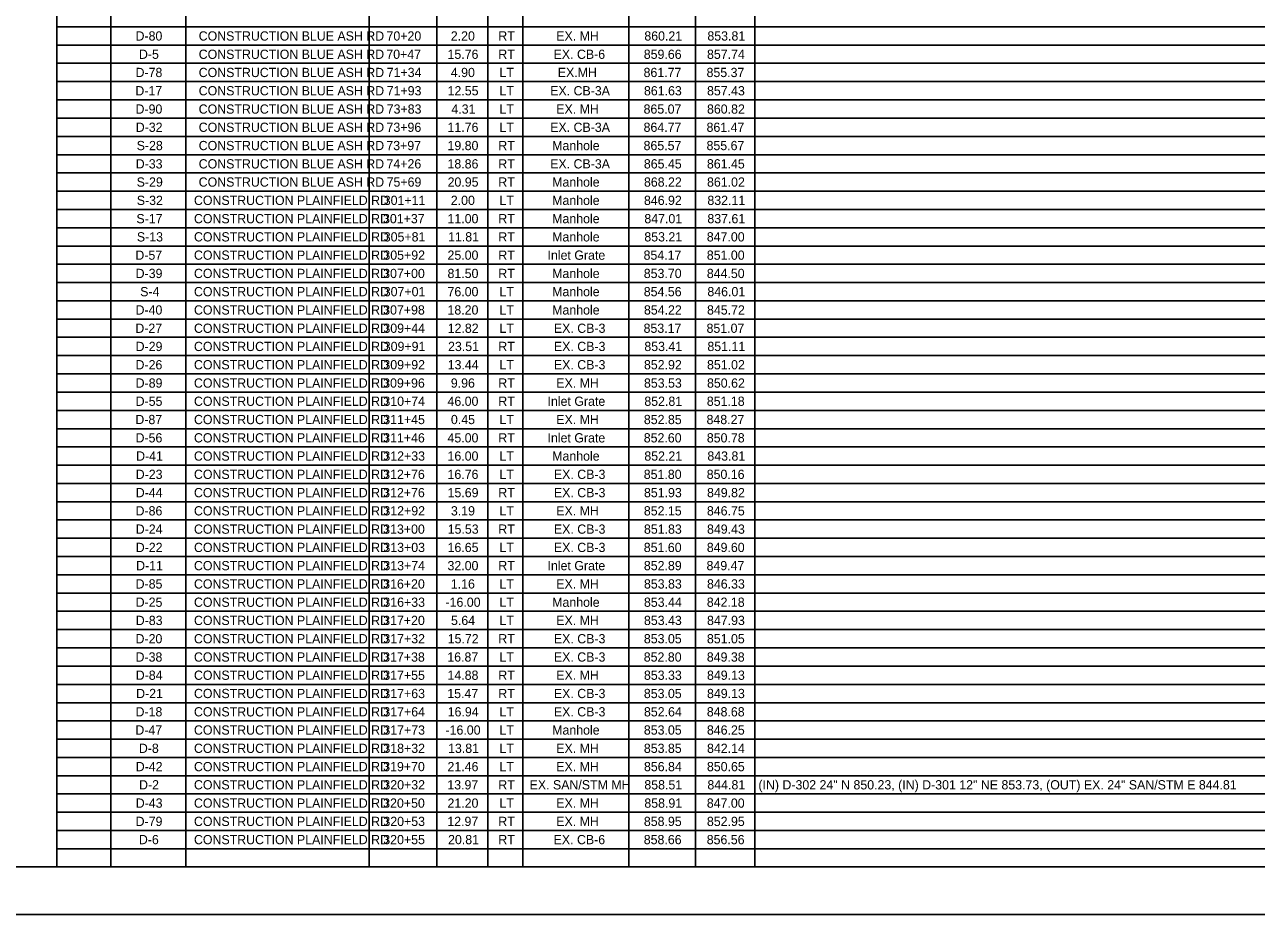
# Model space of a CAD drawing. Extents: x 0 to 34, y 0 to 22.
# Drawn here: x 12.56 to 25.55, y 0 to 9.39 of the extents above; entities that cross this region are included whole.
import ezdxf

# ---------------------------------------------------------------- set-up
doc = ezdxf.new("R2010")
doc.units = 0
for name, color, linetype in [('SH_Border', 7, 'Continuous'), ('SH_Cut_Line', 7, 'Continuous'), ('SH_Text', 7, 'Continuous')]:
    doc.layers.add(name, color=color, linetype=linetype)

msp = doc.modelspace()

# ---------------------------------------------------------------- linework, layer by layer
at = {"layer": 'SH_Border'}
msp.add_lwpolyline([(1.5, 21.5), (33.5, 21.5), (33.5, 0.5), (1.5, 0.5)], close=True, dxfattribs=at)
at = {"layer": 'SH_Cut_Line'}
msp.add_lwpolyline([(0, 0), (34, 0), (34, 22), (0, 22)], close=True, dxfattribs=at)
at = {"layer": 'SH_Text'}
for p, q in [((12.897, 21.5), (12.897, 0.5)), ((13.466, 21.307), (13.466, 0.5)), ((14.256, 21.307), (14.256, 0.5)), ((16.192, 21.307), (16.192, 0.5)), ((16.905, 21.307), (16.905, 0.5)), ((17.444, 21.307), (17.444, 0.5)), ((17.81, 21.307), (17.81, 0.5)), ((18.928, 21.307), (18.928, 0.5)), ((19.631, 21.307), (19.631, 0.5)), ((20.257, 21.307), (20.257, 0.5)), ((12.897, 9.362), (29.601, 9.362)), ((12.897, 9.169), (29.601, 9.169)), ((12.897, 8.977), (29.601, 8.977)), ((12.897, 8.784), (29.601, 8.784)), ((12.897, 8.591), (29.601, 8.591)), ((12.897, 8.399), (29.601, 8.399)), ((12.897, 8.206), (29.601, 8.206)), ((12.897, 8.013), (29.601, 8.013)), ((12.897, 7.821), (29.601, 7.821)), ((12.897, 7.628), (29.601, 7.628)), ((12.897, 7.435), (29.601, 7.435)), ((12.897, 7.243), (29.601, 7.243)), ((12.897, 7.05), (29.601, 7.05)), ((12.897, 6.857), (29.601, 6.857)), ((12.897, 6.665), (29.601, 6.665)), ((12.897, 6.472), (29.601, 6.472)), ((12.897, 6.279), (29.601, 6.279)), ((12.897, 6.087), (29.601, 6.087)), ((12.897, 5.894), (29.601, 5.894)), ((12.897, 5.701), (29.601, 5.701)), ((12.897, 5.509), (29.601, 5.509)), ((12.897, 5.316), (29.601, 5.316)), ((12.897, 5.123), (29.601, 5.123)), ((12.897, 4.931), (29.601, 4.931)), ((12.897, 4.738), (29.601, 4.738)), ((12.897, 4.545), (29.601, 4.545)), ((12.897, 4.353), (29.601, 4.353)), ((12.897, 4.16), (29.601, 4.16)), ((12.897, 3.967), (29.601, 3.967)), ((12.897, 3.775), (29.601, 3.775)), ((12.897, 3.582), (29.601, 3.582)), ((12.897, 3.389), (29.601, 3.389)), ((12.897, 3.197), (29.601, 3.197)), ((12.897, 3.004), (29.601, 3.004)), ((12.897, 2.811), (29.601, 2.811)), ((12.897, 2.619), (29.601, 2.619)), ((12.897, 2.426), (29.601, 2.426)), ((12.897, 2.233), (29.601, 2.233)), ((12.897, 2.041), (29.601, 2.041)), ((12.897, 1.848), (29.601, 1.848)), ((12.897, 1.656), (29.601, 1.656)), ((12.897, 1.463), (29.601, 1.463)), ((12.897, 1.27), (29.601, 1.27)), ((12.897, 1.078), (29.601, 1.078)), ((12.897, 0.885), (29.601, 0.885)), ((12.897, 0.692), (29.601, 0.692)), ((12.897, 0.5), (29.601, 0.5))]:
    msp.add_line(p, q, dxfattribs=at)

# ---------------------------------------------------------------- texts
for s, height, p in [('D-80', 0.0975, (13.727, 9.217)), ('CONSTRUCTION BLUE ASH RD', 0.09749, (14.393, 9.217)), ('70+20', 0.0975, (16.374, 9.217)), ('2.20', 0.0975, (17.052, 9.217)), ('RT', 0.0975, (17.553, 9.217)), ('EX. MH', 0.0975, (18.164, 9.217)), ('860.21', 0.0975, (19.093, 9.217)), ('853.81', 0.0975, (19.758, 9.217)), ('D-5', 0.0975, (13.763, 9.024)), ('CONSTRUCTION BLUE ASH RD', 0.09749, (14.393, 9.024)), ('70+47', 0.0975, (16.372, 9.024)), ('15.76', 0.0975, (17.017, 9.024)), ('RT', 0.0975, (17.553, 9.024)), ('EX. CB-6', 0.0975, (18.136, 9.024)), ('859.66', 0.0975, (19.087, 9.024)), ('857.74', 0.0975, (19.754, 9.024)), ('D-78', 0.0975, (13.727, 8.832)), ('CONSTRUCTION BLUE ASH RD', 0.09749, (14.393, 8.832)), ('71+34', 0.0975, (16.376, 8.832)), ('4.90', 0.0975, (17.052, 8.832)), ('LT', 0.0975, (17.565, 8.832)), ('EX.MH', 0.0975, (18.18, 8.832)), ('861.77', 0.0975, (19.085, 8.832)), ('855.37', 0.0975, (19.749, 8.832)), ('D-17', 0.0975, (13.725, 8.639)), ('CONSTRUCTION BLUE ASH RD', 0.09749, (14.393, 8.639)), ('71+93', 0.0975, (16.376, 8.639)), ('12.55', 0.0975, (17.018, 8.639)), ('LT', 0.0975, (17.565, 8.639)), ('EX. CB-3A', 0.0975, (18.1, 8.639)), ('861.63', 0.0975, (19.089, 8.639)), ('857.43', 0.0975, (19.754, 8.639)), ('D-90', 0.0975, (13.727, 8.446)), ('CONSTRUCTION BLUE ASH RD', 0.09749, (14.393, 8.446)), ('73+83', 0.0975, (16.376, 8.446)), ('4.31', 0.0975, (17.058, 8.446)), ('LT', 0.0975, (17.565, 8.446)), ('EX. MH', 0.0975, (18.164, 8.446)), ('865.07', 0.0975, (19.085, 8.446)), ('860.82', 0.0975, (19.754, 8.446)), ('D-32', 0.0975, (13.729, 8.254)), ('CONSTRUCTION BLUE ASH RD', 0.09749, (14.393, 8.254)), ('73+96', 0.0975, (16.374, 8.254)), ('11.76', 0.0975, (17.017, 8.254)), ('LT', 0.0975, (17.565, 8.254)), ('EX. CB-3A', 0.0975, (18.1, 8.254)), ('864.77', 0.0975, (19.085, 8.254)), ('861.47', 0.0975, (19.749, 8.254)), ('S-28', 0.0975, (13.739, 8.061)), ('CONSTRUCTION BLUE ASH RD', 0.09749, (14.393, 8.061)), ('73+97', 0.0975, (16.372, 8.061)), ('19.80', 0.0975, (17.017, 8.061)), ('RT', 0.0975, (17.553, 8.061)), ('Manhole', 0.0975, (18.121, 8.061)), ('865.57', 0.0975, (19.085, 8.061)), ('855.67', 0.0975, (19.749, 8.061)), ('D-33', 0.0975, (13.729, 7.868)), ('CONSTRUCTION BLUE ASH RD', 0.09749, (14.393, 7.868)), ('74+26', 0.0975, (16.374, 7.868)), ('18.86', 0.0975, (17.017, 7.868)), ('RT', 0.0975, (17.553, 7.868)), ('EX. CB-3A', 0.0975, (18.1, 7.868)), ('865.45', 0.0975, (19.088, 7.868)), ('861.45', 0.0975, (19.753, 7.868)), ('S-29', 0.0975, (13.739, 7.676)), ('CONSTRUCTION BLUE ASH RD', 0.09749, (14.393, 7.676)), ('75+69', 0.0975, (16.375, 7.676)), ('20.95', 0.0975, (17.018, 7.676)), ('RT', 0.0975, (17.553, 7.676)), ('Manhole', 0.0975, (18.121, 7.676)), ('868.22', 0.0975, (19.089, 7.676)), ('861.02', 0.0975, (19.754, 7.676)), ('S-32', 0.0975, (13.74, 7.483)), ('CONSTRUCTION PLAINFIELD RD', 0.09749, (14.343, 7.483)), ('301+11', 0.0975, (16.345, 7.483)), ('2.00', 0.0975, (17.052, 7.483)), ('LT', 0.0975, (17.565, 7.483)), ('Manhole', 0.0975, (18.121, 7.483)), ('846.92', 0.0975, (19.089, 7.483)), ('832.11', 0.0975, (19.758, 7.483)), ('S-17', 0.0975, (13.736, 7.29)), ('CONSTRUCTION PLAINFIELD RD', 0.09749, (14.343, 7.29)), ('301+37', 0.0975, (16.337, 7.29)), ('11.00', 0.0975, (17.017, 7.29)), ('RT', 0.0975, (17.553, 7.29)), ('Manhole', 0.0975, (18.121, 7.29)), ('847.01', 0.0975, (19.093, 7.29)), ('837.61', 0.0975, (19.758, 7.29)), ('S-13', 0.0975, (13.741, 7.098)), ('CONSTRUCTION PLAINFIELD RD', 0.09749, (14.343, 7.098)), ('305+81', 0.0975, (16.345, 7.098)), ('11.81', 0.0975, (17.023, 7.098)), ('RT', 0.0975, (17.553, 7.098)), ('Manhole', 0.0975, (18.121, 7.098)), ('853.21', 0.0975, (19.093, 7.098)), ('847.00', 0.0975, (19.752, 7.098)), ('D-57', 0.0975, (13.725, 6.905)), ('CONSTRUCTION PLAINFIELD RD', 0.09749, (14.343, 6.905)), ('305+92', 0.0975, (16.341, 6.905)), ('25.00', 0.0975, (17.017, 6.905)), ('RT', 0.0975, (17.553, 6.905)), ('Inlet Grate', 0.09749, (18.072, 6.905)), ('854.17', 0.0975, (19.085, 6.905)), ('851.00', 0.0975, (19.752, 6.905)), ('D-39', 0.0975, (13.728, 6.712)), ('CONSTRUCTION PLAINFIELD RD', 0.09749, (14.343, 6.712)), ('307+00', 0.0975, (16.339, 6.712)), ('81.50', 0.0975, (17.017, 6.712)), ('RT', 0.0975, (17.553, 6.712)), ('Manhole', 0.0975, (18.121, 6.712)), ('853.70', 0.0975, (19.087, 6.712)), ('844.50', 0.0975, (19.752, 6.712)), ('S-4', 0.0975, (13.776, 6.52)), ('CONSTRUCTION PLAINFIELD RD', 0.09749, (14.343, 6.52)), ('307+01', 0.0975, (16.345, 6.52)), ('76.00', 0.0975, (17.017, 6.52)), ('LT', 0.0975, (17.565, 6.52)), ('Manhole', 0.0975, (18.121, 6.52)), ('854.56', 0.0975, (19.087, 6.52)), ('846.01', 0.0975, (19.758, 6.52)), ('D-40', 0.0975, (13.727, 6.327)), ('CONSTRUCTION PLAINFIELD RD', 0.09749, (14.343, 6.327)), ('307+98', 0.0975, (16.339, 6.327)), ('18.20', 0.0975, (17.017, 6.327)), ('LT', 0.0975, (17.565, 6.327)), ('Manhole', 0.0975, (18.121, 6.327)), ('854.22', 0.0975, (19.089, 6.327)), ('845.72', 0.0975, (19.754, 6.327)), ('D-27', 0.0975, (13.725, 6.134)), ('CONSTRUCTION PLAINFIELD RD', 0.09749, (14.343, 6.134)), ('309+44', 0.0975, (16.341, 6.134)), ('12.82', 0.0975, (17.019, 6.134)), ('LT', 0.0975, (17.565, 6.134)), ('EX. CB-3', 0.0975, (18.139, 6.134)), ('853.17', 0.0975, (19.085, 6.134)), ('851.07', 0.0975, (19.749, 6.134)), ('D-29', 0.0975, (13.728, 5.942)), ('CONSTRUCTION PLAINFIELD RD', 0.09749, (14.343, 5.942)), ('309+91', 0.0975, (16.345, 5.942)), ('23.51', 0.0975, (17.023, 5.942)), ('RT', 0.0975, (17.553, 5.942)), ('EX. CB-3', 0.0975, (18.139, 5.942)), ('853.41', 0.0975, (19.093, 5.942)), ('851.11', 0.0975, (19.758, 5.942)), ('D-26', 0.0975, (13.727, 5.749)), ('CONSTRUCTION PLAINFIELD RD', 0.09749, (14.343, 5.749)), ('309+92', 0.0975, (16.341, 5.749)), ('13.44', 0.0975, (17.019, 5.749)), ('LT', 0.0975, (17.565, 5.749)), ('EX. CB-3', 0.0975, (18.139, 5.749)), ('852.92', 0.0975, (19.089, 5.749)), ('851.02', 0.0975, (19.754, 5.749)), ('D-89', 0.0975, (13.728, 5.556)), ('CONSTRUCTION PLAINFIELD RD', 0.09749, (14.343, 5.556)), ('309+96', 0.0975, (16.339, 5.556)), ('9.96', 0.0975, (17.052, 5.556)), ('RT', 0.0975, (17.553, 5.556)), ('EX. MH', 0.0975, (18.164, 5.556)), ('853.53', 0.0975, (19.089, 5.556)), ('850.62', 0.0975, (19.754, 5.556)), ('D-55', 0.0975, (13.728, 5.364)), ('CONSTRUCTION PLAINFIELD RD', 0.09749, (14.343, 5.364)), ('310+74', 0.0975, (16.341, 5.364)), ('46.00', 0.0975, (17.017, 5.364)), ('RT', 0.0975, (17.553, 5.364)), ('Inlet Grate', 0.09749, (18.072, 5.364)), ('852.81', 0.0975, (19.093, 5.364)), ('851.18', 0.0975, (19.752, 5.364)), ('D-87', 0.0975, (13.725, 5.171)), ('CONSTRUCTION PLAINFIELD RD', 0.09749, (14.343, 5.171)), ('311+45', 0.0975, (16.34, 5.171)), ('0.45', 0.0975, (17.053, 5.171)), ('LT', 0.0975, (17.565, 5.171)), ('EX. MH', 0.0975, (18.164, 5.171)), ('852.85', 0.0975, (19.088, 5.171)), ('848.27', 0.0975, (19.749, 5.171)), ('D-56', 0.0975, (13.727, 4.978)), ('CONSTRUCTION PLAINFIELD RD', 0.09749, (14.343, 4.978)), ('311+46', 0.0975, (16.339, 4.978)), ('45.00', 0.0975, (17.017, 4.978)), ('RT', 0.0975, (17.553, 4.978)), ('Inlet Grate', 0.09749, (18.072, 4.978)), ('852.60', 0.0975, (19.087, 4.978)), ('850.78', 0.0975, (19.752, 4.978)), ('D-41', 0.0975, (13.733, 4.786)), ('CONSTRUCTION PLAINFIELD RD', 0.09749, (14.343, 4.786)), ('312+33', 0.0975, (16.341, 4.786)), ('16.00', 0.0975, (17.017, 4.786)), ('LT', 0.0975, (17.565, 4.786)), ('Manhole', 0.0975, (18.121, 4.786)), ('852.21', 0.0975, (19.093, 4.786)), ('843.81', 0.0975, (19.758, 4.786)), ('D-23', 0.0975, (13.729, 4.593)), ('CONSTRUCTION PLAINFIELD RD', 0.09749, (14.343, 4.593)), ('312+76', 0.0975, (16.339, 4.593)), ('16.76', 0.0975, (17.017, 4.593)), ('LT', 0.0975, (17.565, 4.593)), ('EX. CB-3', 0.0975, (18.139, 4.593)), ('851.80', 0.0975, (19.087, 4.593)), ('850.16', 0.0975, (19.751, 4.593)), ('D-44', 0.0975, (13.729, 4.4)), ('CONSTRUCTION PLAINFIELD RD', 0.09749, (14.343, 4.4)), ('312+76', 0.0975, (16.339, 4.4)), ('15.69', 0.0975, (17.018, 4.4)), ('RT', 0.0975, (17.553, 4.4)), ('EX. CB-3', 0.0975, (18.139, 4.4)), ('851.93', 0.0975, (19.089, 4.4)), ('849.82', 0.0975, (19.754, 4.4)), ('D-86', 0.0975, (13.727, 4.208)), ('CONSTRUCTION PLAINFIELD RD', 0.09749, (14.343, 4.208)), ('312+92', 0.0975, (16.341, 4.208)), ('3.19', 0.0975, (17.053, 4.208)), ('LT', 0.0975, (17.565, 4.208)), ('EX. MH', 0.0975, (18.164, 4.208)), ('852.15', 0.0975, (19.088, 4.208)), ('846.75', 0.0975, (19.753, 4.208)), ('D-24', 0.0975, (13.729, 4.015)), ('CONSTRUCTION PLAINFIELD RD', 0.09749, (14.343, 4.015)), ('313+00', 0.0975, (16.339, 4.015)), ('15.53', 0.0975, (17.019, 4.015)), ('RT', 0.0975, (17.553, 4.015)), ('EX. CB-3', 0.0975, (18.139, 4.015)), ('851.83', 0.0975, (19.089, 4.015)), ('849.43', 0.0975, (19.754, 4.015)), ('D-22', 0.0975, (13.729, 3.822)), ('CONSTRUCTION PLAINFIELD RD', 0.09749, (14.343, 3.822)), ('313+03', 0.0975, (16.341, 3.822)), ('16.65', 0.0975, (17.018, 3.822)), ('LT', 0.0975, (17.565, 3.822)), ('EX. CB-3', 0.0975, (18.139, 3.822)), ('851.60', 0.0975, (19.087, 3.822)), ('849.60', 0.0975, (19.752, 3.822)), ('D-11', 0.0975, (13.733, 3.63)), ('CONSTRUCTION PLAINFIELD RD', 0.09749, (14.343, 3.63)), ('313+74', 0.0975, (16.341, 3.63)), ('32.00', 0.0975, (17.017, 3.63)), ('RT', 0.0975, (17.553, 3.63)), ('Inlet Grate', 0.09749, (18.072, 3.63)), ('852.89', 0.0975, (19.088, 3.63)), ('849.47', 0.0975, (19.749, 3.63)), ('D-85', 0.0975, (13.728, 3.437)), ('CONSTRUCTION PLAINFIELD RD', 0.09749, (14.343, 3.437)), ('316+20', 0.0975, (16.339, 3.437)), ('1.16', 0.0975, (17.052, 3.437)), ('LT', 0.0975, (17.565, 3.437)), ('EX. MH', 0.0975, (18.164, 3.437)), ('853.83', 0.0975, (19.089, 3.437)), ('846.33', 0.0975, (19.754, 3.437)), ('D-25', 0.0975, (13.728, 3.244)), ('CONSTRUCTION PLAINFIELD RD', 0.09749, (14.343, 3.244)), ('316+33', 0.0975, (16.341, 3.244)), ('-16.00', 0.0975, (16.996, 3.244)), ('LT', 0.0975, (17.565, 3.244)), ('Manhole', 0.0975, (18.121, 3.244)), ('853.44', 0.0975, (19.089, 3.244)), ('842.18', 0.0975, (19.752, 3.244)), ('D-83', 0.0975, (13.729, 3.052)), ('CONSTRUCTION PLAINFIELD RD', 0.09749, (14.343, 3.052)), ('317+20', 0.0975, (16.339, 3.052)), ('5.64', 0.0975, (17.054, 3.052)), ('LT', 0.0975, (17.565, 3.052)), ('EX. MH', 0.0975, (18.164, 3.052)), ('853.43', 0.0975, (19.089, 3.052)), ('847.93', 0.0975, (19.754, 3.052)), ('D-20', 0.0975, (13.727, 2.859)), ('CONSTRUCTION PLAINFIELD RD', 0.09749, (14.343, 2.859)), ('317+32', 0.0975, (16.341, 2.859)), ('15.72', 0.0975, (17.019, 2.859)), ('RT', 0.0975, (17.553, 2.859)), ('EX. CB-3', 0.0975, (18.139, 2.859)), ('853.05', 0.0975, (19.088, 2.859)), ('851.05', 0.0975, (19.753, 2.859)), ('D-38', 0.0975, (13.727, 2.666)), ('CONSTRUCTION PLAINFIELD RD', 0.09749, (14.343, 2.666)), ('317+38', 0.0975, (16.339, 2.666)), ('16.87', 0.0975, (17.015, 2.666)), ('LT', 0.0975, (17.565, 2.666)), ('EX. CB-3', 0.0975, (18.139, 2.666)), ('852.80', 0.0975, (19.087, 2.666)), ('849.38', 0.0975, (19.752, 2.666)), ('D-84', 0.0975, (13.729, 2.474)), ('CONSTRUCTION PLAINFIELD RD', 0.09749, (14.343, 2.474)), ('317+55', 0.0975, (16.34, 2.474)), ('14.88', 0.0975, (17.017, 2.474)), ('RT', 0.0975, (17.553, 2.474)), ('EX. MH', 0.0975, (18.164, 2.474)), ('853.33', 0.0975, (19.089, 2.474)), ('849.13', 0.0975, (19.754, 2.474)), ('D-21', 0.0975, (13.733, 2.281)), ('CONSTRUCTION PLAINFIELD RD', 0.09749, (14.343, 2.281)), ('317+63', 0.0975, (16.341, 2.281)), ('15.47', 0.0975, (17.015, 2.281)), ('RT', 0.0975, (17.553, 2.281)), ('EX. CB-3', 0.0975, (18.139, 2.281)), ('853.05', 0.0975, (19.088, 2.281)), ('849.13', 0.0975, (19.754, 2.281)), ('D-18', 0.0975, (13.727, 2.088)), ('CONSTRUCTION PLAINFIELD RD', 0.09749, (14.343, 2.088)), ('317+64', 0.0975, (16.341, 2.088)), ('16.94', 0.0975, (17.019, 2.088)), ('LT', 0.0975, (17.565, 2.088)), ('EX. CB-3', 0.0975, (18.139, 2.088)), ('852.64', 0.0975, (19.089, 2.088)), ('848.68', 0.0975, (19.752, 2.088)), ('D-47', 0.0975, (13.725, 1.896)), ('CONSTRUCTION PLAINFIELD RD', 0.09749, (14.343, 1.896)), ('317+73', 0.0975, (16.341, 1.896)), ('-16.00', 0.0975, (16.996, 1.896)), ('LT', 0.0975, (17.565, 1.896)), ('Manhole', 0.0975, (18.121, 1.896)), ('853.05', 0.0975, (19.088, 1.896)), ('846.25', 0.0975, (19.753, 1.896)), ('D-8', 0.0975, (13.762, 1.703)), ('CONSTRUCTION PLAINFIELD RD', 0.09749, (14.343, 1.703)), ('318+32', 0.0975, (16.341, 1.703)), ('13.81', 0.0975, (17.023, 1.703)), ('LT', 0.0975, (17.565, 1.703)), ('EX. MH', 0.0975, (18.164, 1.703)), ('853.85', 0.0975, (19.088, 1.703)), ('842.14', 0.0975, (19.754, 1.703)), ('D-42', 0.0975, (13.729, 1.51)), ('CONSTRUCTION PLAINFIELD RD', 0.09749, (14.343, 1.51)), ('319+70', 0.0975, (16.339, 1.51)), ('21.46', 0.0975, (17.017, 1.51)), ('LT', 0.0975, (17.565, 1.51)), ('EX. MH', 0.0975, (18.164, 1.51)), ('856.84', 0.0975, (19.089, 1.51)), ('850.65', 0.0975, (19.753, 1.51)), ('D-2', 0.0975, (13.764, 1.318)), ('CONSTRUCTION PLAINFIELD RD', 0.09749, (14.343, 1.318)), ('320+32', 0.0975, (16.341, 1.318)), ('13.97', 0.0975, (17.015, 1.318)), ('RT', 0.0975, (17.553, 1.318)), ('EX. SAN/STM MH', 0.09749, (17.883, 1.318)), ('858.51', 0.0975, (19.093, 1.318)), ('844.81', 0.0975, (19.758, 1.318)), ('(IN) D-302 24" N 850.23, (IN) D-301 12" NE 853.73, (OUT) EX. 24" SAN/STM E 844.81', 0.09749, (20.296, 1.318)), ('D-43', 0.0975, (13.729, 1.125)), ('CONSTRUCTION PLAINFIELD RD', 0.09749, (14.343, 1.125)), ('320+50', 0.0975, (16.339, 1.125)), ('21.20', 0.0975, (17.017, 1.125)), ('LT', 0.0975, (17.565, 1.125)), ('EX. MH', 0.0975, (18.164, 1.125)), ('858.91', 0.0975, (19.093, 1.125)), ('847.00', 0.0975, (19.752, 1.125)), ('D-79', 0.0975, (13.728, 0.932)), ('CONSTRUCTION PLAINFIELD RD', 0.09749, (14.343, 0.932)), ('320+53', 0.0975, (16.341, 0.932)), ('12.97', 0.0975, (17.015, 0.932)), ('RT', 0.0975, (17.553, 0.932)), ('EX. MH', 0.0975, (18.164, 0.932)), ('858.95', 0.0975, (19.088, 0.932)), ('852.95', 0.0975, (19.753, 0.932)), ('D-6', 0.0975, (13.762, 0.74)), ('CONSTRUCTION PLAINFIELD RD', 0.09749, (14.343, 0.74)), ('320+55', 0.0975, (16.34, 0.74)), ('20.81', 0.0975, (17.023, 0.74)), ('RT', 0.0975, (17.553, 0.74)), ('EX. CB-6', 0.0975, (18.136, 0.74)), ('858.66', 0.0975, (19.087, 0.74)), ('856.56', 0.0975, (19.751, 0.74))]:
    msp.add_text(s, height=height, dxfattribs=at).set_placement(p)

doc.saveas('drawing.dxf')
